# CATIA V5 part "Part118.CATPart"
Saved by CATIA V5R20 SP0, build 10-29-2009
Part number: FA 084700-2 comprimido
Revision: ANY
Definition: UNKNOWN
Nomenclature: FA 084700-2 comprimido
Source: Unknown
Bounding box of the stored display mesh (mm): x -2.45 to 2.45, y 0 to 4.72, z -2.45 to 2.45
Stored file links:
  C:\Users\Utente\Desktop\IO LAVORO\3D X SITO CF\CUMSA\3D files FA\FA 084700\Part118.CATPart

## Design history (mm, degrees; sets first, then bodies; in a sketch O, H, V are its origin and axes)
Body1 "Cortar-Extruir1" (main body)
  Solid1: solid without history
